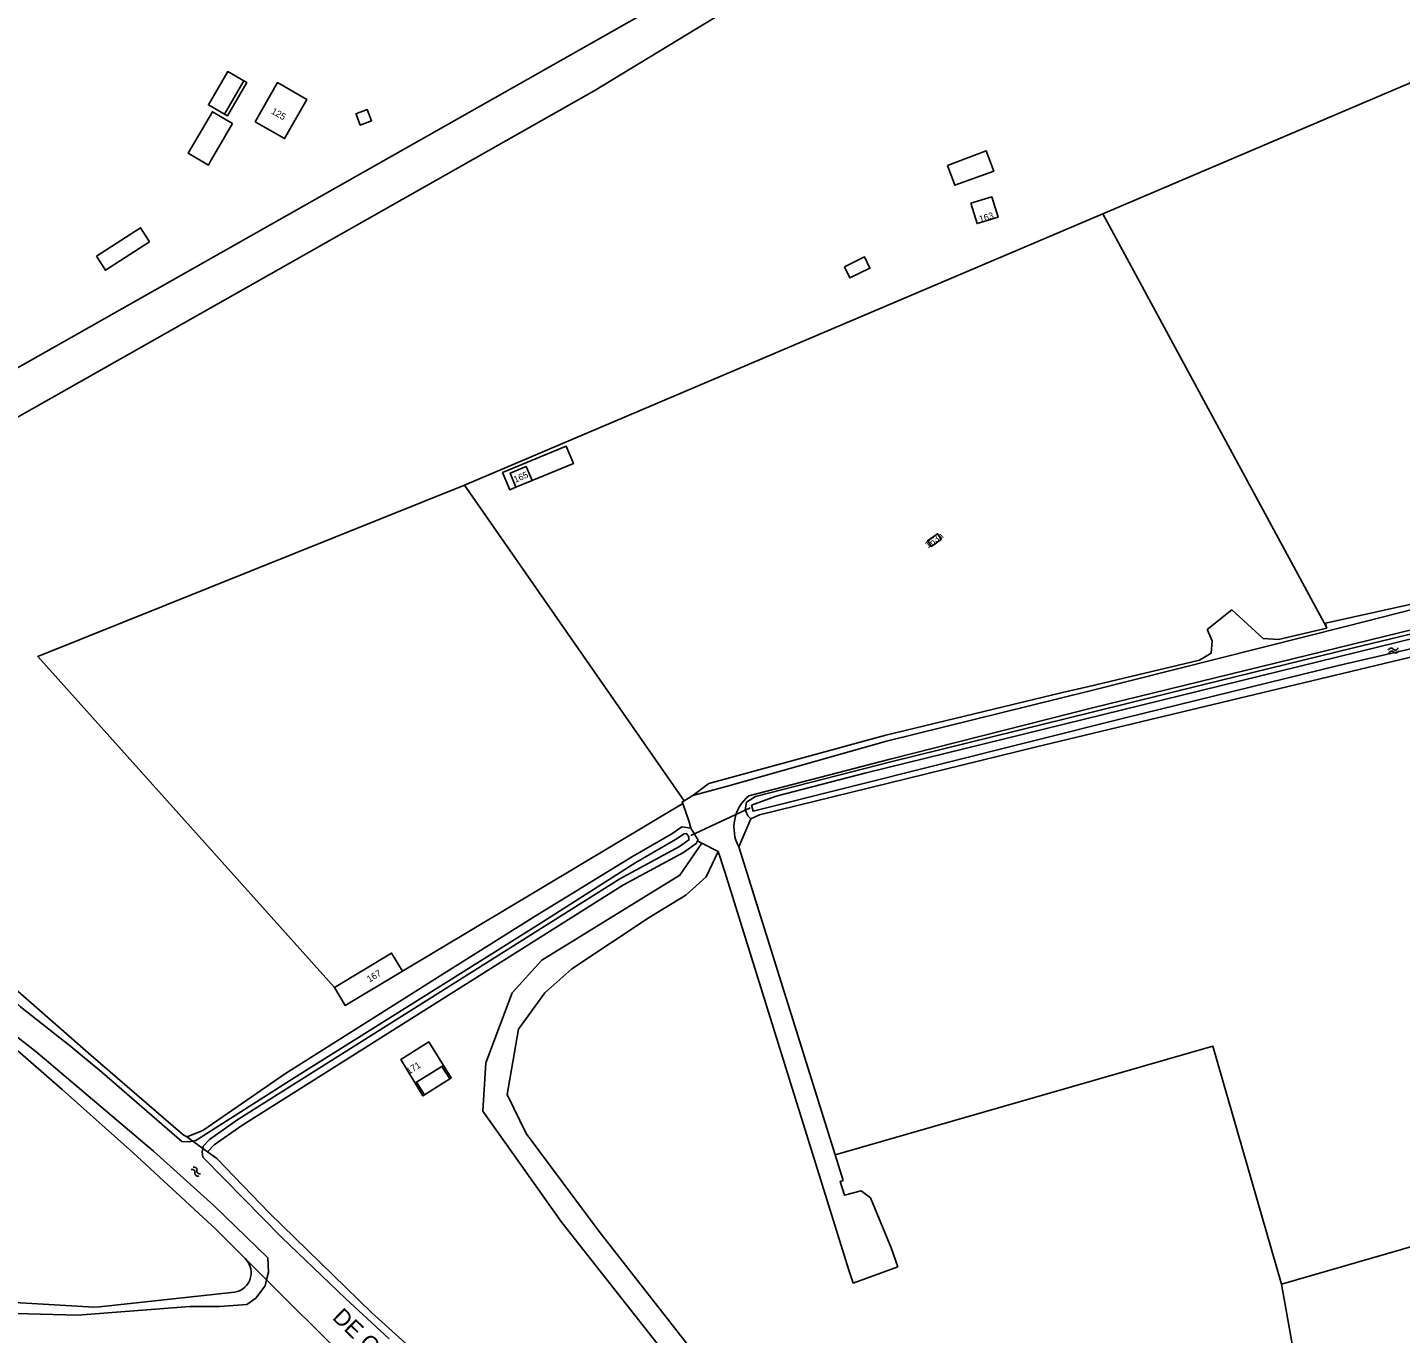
# Model space of a CAD drawing. Extents: x 126000 to 131009, y 393000 to 395500.
# Drawn here: x 129419 to 129626.1, y 394883.3 to 395080.3 of the extents above; entities that cross this region are included whole.
import ezdxf

# ---------------------------------------------------------------- set-up
doc = ezdxf.new("R2010")
doc.units = 0
for name, color, linetype in [('gg-afsc-draadraster', 7, 'Continuous'), ('gg-afsc-hekwerk', 7, 'Continuous'), ('gg-afsc-muur', 7, 'Continuous'), ('gg-anno-huisnummerreeks BGT', 7, 'Continuous'), ('gg-anno-naam water', 7, 'Continuous'), ('gg-bbg-bijgebouw', 7, 'Continuous'), ('gg-bbg-gedigitaliseerde bijgebouw', 7, 'Continuous'), ('gg-bbg-hoofdgebouw', 7, 'Continuous'), ('gg-bbg-luifel en loopbrug', 7, 'Continuous'), ('gg-knt-onverhard', 7, 'Continuous'), ('gg-kntw-bovenkant insteek waterloop', 7, 'Continuous'), ('gg-kntw-waterlijn', 7, 'Continuous'), ('gg-kwrk-duiker nz buis', 7, 'Continuous'), ('gt-grn-groengrens', 7, 'Continuous'), ('gt-grn-vlakafsluiter', 7, 'Continuous'), ('gt-symb-watersymbool', 7, 'Continuous')]:
    doc.layers.add(name, color=color, linetype=linetype)

# ---------------------------------------------------------------- blocks, each defined once
blk = doc.blocks.new('gt0-WA')
at = {"layer": 'gt-symb-watersymbool'}
for centre, start, end in [((-0.32, 0.02), 28.0725, 151.9275), ((0.43, 0.42), 208.0725, 331.9275), ((-0.32, -0.43), 28.0725, 151.9275), ((0.43, -0.03), 208.0725, 331.9275)]:
    blk.add_arc(centre, 0.425, start, end, dxfattribs=at)

msp = doc.modelspace()

# ---------------------------------------------------------------- linework, layer by layer
at = {"layer": 'gg-afsc-draadraster'}
for p, q in [((129575.11, 394979.98), (129548.48, 394973.56)), ((129540.85, 394910.31), (129526.29, 394956.72)), ((129542.06, 394906.43), (129540.85, 394910.31))]:
    msp.add_line(p, q, dxfattribs=at)
for points in [[(129614.94, 394989.85), (129614.8, 394990.48), (129637.5, 394995.48), (129652.52, 394998.98), (129658.89, 395001.74), (129662.61, 395002.72), (129673.9, 395005.45), (129695.98, 395011.75), (129716.35, 395017.48), (129748.21, 395026.52)], [(129600.65, 394992.48), (129605.4, 394988.16), (129607.67, 394987.97), (129614.97, 394989.7), (129614.94, 394989.85)], [(129579.11, 394980.93), (129595.76, 394984.87), (129597.56, 394985.93), (129597.7, 394987.79), (129596.95, 394989.5)]]:
    msp.add_lwpolyline(points, dxfattribs=at)
at = {"layer": 'gg-afsc-hekwerk'}
for p, q in [((129596.95, 394989.5), (129600.65, 394992.48)), ((129579.11, 394980.93), (129575.11, 394979.98)), ((129519.35, 394964.46), (129518.06, 394963.67)), ((129517.86, 394963.26), (129518.81, 394960.5)), ((129520.09, 394957.61), (129520.74, 394957.27)), ((129520.74, 394957.27), (129523.2, 394956)), ((129550.29, 394893.41), (129549.26, 394896.25))]:
    msp.add_line(p, q, dxfattribs=at)
for points in [[(129548.48, 394973.56), (129521.76, 394966.28), (129519.35, 394964.46)], [(129518.06, 394963.67), (129517.91, 394963.58), (129517.76, 394963.53), (129517.86, 394963.26)], [(129523.2, 394956), (129524.19, 394952.95), (129542.91, 394892.9), (129543.57, 394890.94)]]:
    msp.add_lwpolyline(points, dxfattribs=at)
at = {"layer": 'gg-afsc-muur'}
for p, q in [((129482.71, 394921.74), (129481.52, 394923.62)), ((129478.9, 394919.33), (129477.71, 394921.22))]:
    msp.add_line(p, q, dxfattribs=at)
at = {"layer": 'gg-bbg-bijgebouw'}
msp.add_line((129448.74, 395067.2), (129451.65, 395072.22), dxfattribs=at)
for points in [[(129451.65, 395072.22), (129449.22, 395073.63), (129446.32, 395068.61), (129448.74, 395067.2)], [(129468.57, 395067.23), (129468.56, 395067.26), (129470.24, 395067.9), (129470.88, 395066.2), (129469.2, 395065.57), (129468.57, 395067.23)], [(129542.24, 395044.21), (129543.06, 395042.52), (129546.08, 395043.97), (129545.26, 395045.67), (129542.24, 395044.21)]]:
    msp.add_lwpolyline(points, dxfattribs=at)
at = {"layer": 'gg-bbg-gedigitaliseerde bijgebouw'}
msp.add_lwpolyline([(129429.41, 395045.78), (129436.06, 395050.07), (129437.42, 395047.96), (129430.77, 395043.67), (129429.41, 395045.78)], dxfattribs=at)
at = {"layer": 'gg-bbg-hoofdgebouw'}
for p, q in [((129492.67, 395010.96), (129495.12, 395011.97)), ((129477.71, 394921.22), (129481.52, 394923.62)), ((129481.52, 394923.62), (129481.76, 394923.77)), ((129477.49, 394921.08), (129477.71, 394921.22))]:
    msp.add_line(p, q, dxfattribs=at)
for points in [[(129453.34, 395066.04), (129457.79, 395063.52), (129461.15, 395069.44), (129456.71, 395071.96), (129453.34, 395066.04)], [(129561.3, 395053.77), (129562.23, 395050.71), (129565.39, 395051.68), (129564.46, 395054.74), (129561.3, 395053.77)], [(129495.12, 395011.97), (129494.25, 395014.07), (129491.81, 395013.06), (129492.67, 395010.96)], [(129556.85, 395003.13), (129556.27, 395003.95), (129554.75, 395002.85), (129555.34, 395002.04), (129556.85, 395003.13)], [(129465.31, 394935.5), (129473.93, 394940.7), (129475.56, 394937.99)], [(129475.56, 394937.99), (129466.95, 394932.8), (129465.31, 394935.5)], [(129481.76, 394923.77), (129479.54, 394927.31), (129475.31, 394924.65), (129477.49, 394921.08)]]:
    msp.add_lwpolyline(points, dxfattribs=at)
at = {"layer": 'gg-bbg-luifel en loopbrug'}
msp.add_line((129478.9, 394919.33), (129482.71, 394921.74), dxfattribs=at)
for points in [[(129451.65, 395072.22), (129452.08, 395071.97), (129449.17, 395066.94), (129448.74, 395067.2)], [(129449.96, 395065.8), (129446.64, 395060.1), (129446.31, 395059.54), (129443.27, 395061.31), (129446.92, 395067.58), (129449.96, 395065.8)], [(129557.77, 395059.48), (129558.87, 395056.49), (129564.74, 395058.63), (129563.61, 395061.69), (129557.77, 395059.48)], [(129492.67, 395010.96), (129491.75, 395010.58), (129490.68, 395013.17), (129500.28, 395017.14), (129501.35, 395014.55), (129495.12, 395011.97)], [(129481.76, 394923.77), (129482.94, 394921.91), (129482.71, 394921.74)], [(129477.49, 394921.08), (129478.67, 394919.17), (129478.9, 394919.33)]]:
    msp.add_lwpolyline(points, dxfattribs=at)
at = {"layer": 'gg-knt-onverhard'}
for points in [[(129613.28, 395141.08), (129582.5, 395124.65), (129519.7, 395086.8), (129393.06, 395015.14), (129396.26, 395009.49), (129504.47, 395070.72), (129579.33, 395116.22), (129615.12, 395138.08)], [(129748.77, 395025.42), (129716.46, 395016.33), (129661.96, 395001.19), (129618, 394989.99), (129579.09, 394980.2), (129548.59, 394972.67), (129524.61, 394965.9), (129519.35, 394964.46)], [(129751.05, 395022.65), (129697.21, 395007.57), (129663.11, 394998.07), (129579.64, 394977.71), (129549.15, 394969.95), (129527.8, 394964.44)], [(129523.2, 394956), (129521.36, 394952.22), (129518.3, 394949.46), (129512.76, 394946.09), (129501.12, 394938.35), (129497.07, 394934.73), (129493.09, 394929.24), (129491.39, 394919.38), (129494.23, 394913.5), (129505.22, 394898.71), (129523.85, 394874.97), (129532.29, 394859.43), (129538.43, 394851.91), (129535.72, 394849.7), (129528.34, 394858.73), (129520.33, 394873.81), (129499.63, 394900.07), (129487.69, 394916.87), (129488.16, 394924.17), (129492.14, 394934.69), (129496.59, 394939.62), (129517.43, 394952.44), (129520.74, 394957.27)]]:
    msp.add_lwpolyline(points, dxfattribs=at)
msp.add_arc((129531.88, 394959.63), 6.31, 130.3012, 207.4987, dxfattribs=at)
at = {"layer": 'gg-kntw-bovenkant insteek waterloop'}
for p, q in [((129529.43, 394961.55), (129528.1, 394960.93)), ((129519.06, 394959.53), (129517.7, 394959.73)), ((129519.86, 394957.25), (129520.09, 394957.61))]:
    msp.add_line(p, q, dxfattribs=at)
for points in [[(129528.1, 394960.93), (129527.67, 394961.38), (129527.24, 394962.3), (129527.48, 394963.47), (129528.84, 394964.3), (129549.25, 394969.55), (129579.77, 394977.06), (129596.24, 394981.18), (129619, 394986.73), (129663.26, 394997.37), (129697.81, 395006.7), (129717.08, 395011.55), (129744.88, 395019.08), (129758.77, 395021.96)], [(129641.88, 394988.76), (129571.21, 394971.83), (129529.43, 394961.55)], [(129355.95, 394958.69), (129360.54, 394954.13), (129364.69, 394950.63), (129369.4, 394947.54), (129373.43, 394945.12), (129378.36, 394942.81), (129383.3, 394941.24), (129393.72, 394939.24), (129398.48, 394938.24), (129402.62, 394936.9), (129406.48, 394934.93), (129410.51, 394931.94), (129414.77, 394928.39), (129424.25, 394920.16), (129434.93, 394910.63), (129447.49, 394899.01), (129451.87, 394894.63)], [(129517.7, 394959.73), (129516.18, 394958.71), (129510.25, 394955.29), (129495.61, 394946.29), (129481.83, 394937.64), (129457.93, 394922.55), (129445.45, 394913.95), (129443.08, 394912.98)], [(129519.06, 394959.53), (129520.16, 394957.72), (129520.09, 394957.61)], [(129446.17, 394910.72), (129447.16, 394911.8), (129451.34, 394914.71), (129508.9, 394950.98), (129517.94, 394955.89), (129519.86, 394957.25)], [(129443.08, 394912.98), (129442.45, 394913.37), (129428.59, 394925.33), (129414.68, 394937.45), (129409.74, 394941.4), (129406.96, 394943.31), (129403.56, 394944.21), (129399.14, 394945.1), (129394.55, 394945.76), (129389.62, 394946.25), (129384.97, 394947.08), (129381.01, 394948.26), (129377.09, 394949.94), (129373.69, 394951.74), (129371.96, 394953.06)], [(129528.11, 394769.87), (129528.57, 394774), (129529.54, 394785.38), (129530.26, 394792.07), (129530.29, 394797.9), (129529.87, 394804.13), (129528.7, 394814.94), (129527.14, 394822.75), (129525.19, 394831.74), (129523.52, 394837.91), (129521.64, 394842.26), (129519.7, 394845.37), (129517.15, 394847.74), (129514.02, 394849.65), (129510.73, 394851.45), (129507.16, 394853.53), (129503.98, 394855.56), (129500.29, 394858.83), (129494.95, 394863.74), (129486.54, 394872.37), (129470.92, 394886.53), (129455.46, 394901.53), (129447.56, 394909.71), (129446.17, 394910.72)], [(129409.33, 394888.46), (129428.22, 394887.35), (129429.04, 394887.33), (129429.87, 394887.38), (129449.81, 394889.51)]]:
    msp.add_lwpolyline(points, dxfattribs=at)
msp.add_arc((129449.75, 394892.51), 3, 271.1157, 45.0271, dxfattribs=at)
at = {"layer": 'gg-kntw-waterlijn'}
for points in [[(129528.19, 394962.99), (129531.92, 394964.36), (129545.49, 394967.89), (129708.92, 395008.04)], [(129642.02, 394989.9), (129616.73, 394984.05), (129584.55, 394976.19), (129528.44, 394962.1), (129528.19, 394962.99)], [(129455.08, 394891.43), (129455.38, 394892.59), (129455.28, 394894.77), (129447.12, 394902.65), (129438.02, 394910.82), (129420.26, 394925.86), (129413.89, 394930.79), (129410.13, 394934.02), (129406.85, 394936.55), (129404.64, 394937.97), (129401.29, 394939.34), (129396.94, 394940.55), (129390.33, 394941.75), (129384.06, 394942.65), (129378.49, 394944.26), (129372.98, 394947.02), (129365.71, 394951.76), (129360.22, 394956.1), (129357.55, 394958.86), (129360.04, 394961.33), (129361.05, 394961.26), (129362.25, 394961.54)], [(129445.46, 394911.24), (129445.53, 394911.59), (129446.46, 394912.61), (129450.75, 394915.59), (129508.37, 394951.9), (129517.38, 394956.78), (129518.78, 394957.78), (129518.76, 394958.24), (129518.4, 394958.74), (129518.07, 394958.71), (129516.74, 394957.81), (129510.79, 394954.38), (129496.35, 394945.18), (129482.56, 394936.51), (129459.24, 394921.92), (129444.4, 394912.44), (129443.94, 394912.35)], [(129442.32, 394912.32), (129430.23, 394922.77), (129425.55, 394926.63), (129417.99, 394932.58), (129414.06, 394936.51), (129406.87, 394941.78), (129402.63, 394943.38), (129398.6, 394944.17), (129389.66, 394945.27), (129384.86, 394946.17), (129380.82, 394947.26), (129376.41, 394949.07), (129371, 394952.37), (129370.79, 394954.09)], [(129443.94, 394912.35), (129443.36, 394912.24), (129442.32, 394912.32)], [(129445.46, 394909.92), (129445.37, 394910.75), (129445.46, 394911.24)], [(129473.55, 394882.55), (129467, 394888.63), (129457.35, 394897.88), (129448.75, 394906.63), (129445.46, 394909.92)], [(129455.08, 394891.43), (129454.85, 394890.51), (129453.46, 394888.65), (129452.12, 394887.74), (129447.98, 394887.4), (129443.5, 394887.4), (129426.61, 394886.11), (129413.39, 394886.47)]]:
    msp.add_lwpolyline(points, dxfattribs=at)
at = {"layer": 'gg-kwrk-duiker nz buis'}
msp.add_line((129528.01, 394962.59), (129519.08, 394958.46), dxfattribs=at)
at = {"layer": 'gt-grn-groengrens'}
for p, q in [((129581.21, 395052.17), (129688.01, 395097.71)), ((129581.21, 395052.17), (129484.92, 395011.28)), ((129614.94, 394989.85), (129581.21, 395052.17)), ((129518.06, 394963.67), (129484.92, 395011.28)), ((129475.56, 394937.99), (129517.86, 394963.26)), ((129518.81, 394960.5), (129519.06, 394959.53)), ((129787.02, 394942.27), (129608.12, 394890.8)), ((129543.57, 394890.94), (129550.29, 394893.41))]:
    msp.add_line(p, q, dxfattribs=at)
for points in [[(129484.92, 395011.28), (129420.57, 394985.43), (129465.31, 394935.5)], [(129608.12, 394890.8), (129597.8, 394926.69), (129540.85, 394910.31)], [(129549.26, 394896.25), (129546.15, 394903.8), (129544.77, 394904.87), (129542.26, 394904.19), (129541.59, 394906.28), (129542.06, 394906.43)]]:
    msp.add_lwpolyline(points, dxfattribs=at)
at = {"layer": 'gt-grn-vlakafsluiter'}
for p, q in [((129528.1, 394960.93), (129526.29, 394956.72)), ((129443.08, 394912.98), (129443.94, 394912.35)), ((129443.94, 394912.35), (129445.46, 394911.24)), ((129445.46, 394911.24), (129446.17, 394910.72)), ((129451.87, 394894.63), (129455.08, 394891.43)), ((129455.08, 394891.43), (129466.38, 394880.17)), ((129625.23, 394796.29), (129608.12, 394890.8))]:
    msp.add_line(p, q, dxfattribs=at)

# ---------------------------------------------------------------- block references
at = {"layer": 'gt-symb-watersymbool'}
for p, rotation in [((129624.98, 394986.31), 13.411071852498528), ((129444.38, 394907.8), -39.72486253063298)]:
    msp.add_blockref('gt0-WA', p, dxfattribs=dict(at, rotation=rotation))

# ---------------------------------------------------------------- texts
at = {"layer": 'gg-anno-huisnummerreeks BGT'}
for s, rotation, p in [('125', 330.4, (129455.69, 395067.36)), ('163', 17, (129562.7, 395050.86)), ('165', 22.4, (129492.58, 395011.61)), ('163a', 35.9, (129554.82, 395001.69)), ('167', 31.1, (129470.58, 394936.25)), ('171', 32.2, (129476.55, 394922.37))]:
    msp.add_text(s, height=1, rotation=rotation, dxfattribs=at).set_placement(p)
at = {"layer": 'gg-anno-naam water'}
msp.add_text('DE OUDE LEIJ', height=2.5, rotation=316.0534, dxfattribs=at).set_placement((129464.86, 394885.61))

doc.saveas('drawing.dxf')
